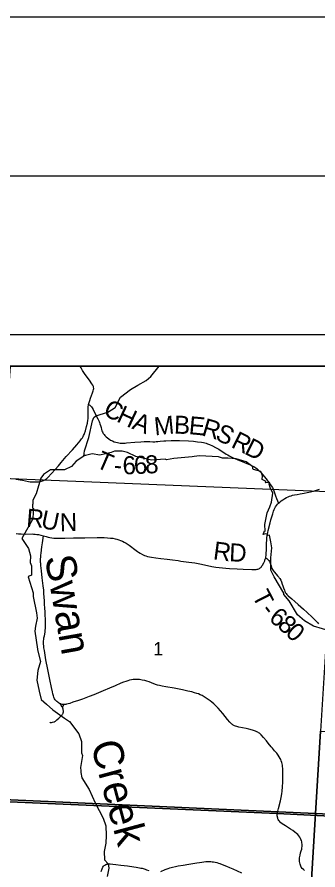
# Model space of a CAD drawing. Extents: x -2.1 to 31.9, y 6.3 to 28.3.
# Drawn here: x 4.749 to 5.698, y 25.658 to 28.344 of the extents above; entities that cross this region are included whole.
import ezdxf

# ---------------------------------------------------------------- set-up
doc = ezdxf.new("R2010")
doc.units = 0
for name, color, linetype in [('Default', 7, 'Continuous'), ('GM_X_County_Road', 7, 'Continuous'), ('GM_X_County_Road_Text', 7, 'Continuous'), ('GM_X_Minor_River', 7, 'Continuous'), ('GM_X_Minor_River_Text', 7, 'Continuous'), ('GM_X_Section', 7, 'Continuous'), ('GM_X_Section_Text', 7, 'Continuous'), ('GM_X_Township_Road', 7, 'Continuous'), ('GM_X_Township_Road_Text', 7, 'Continuous'), ('SH_Border', 7, 'Continuous'), ('SH_Cut_Line', 7, 'Continuous'), ('SH_Data', 7, 'Continuous')]:
    doc.layers.add(name, color=color, linetype=linetype)

msp = doc.modelspace()

# ---------------------------------------------------------------- linework, layer by layer
at = {"layer": 'Default'}
for points in [[(4.6286, 25.8765), (5.5694, 25.8349), (6.8344, 25.7721), (6.8344, 27.244), (4.7331, 27.244)], [(6.8344, 20.444), (6.8344, 25.7721), (5.5694, 25.8349), (4.6286, 25.8765), (4.6032, 25.4816), (4.5667, 24.9084), (4.5473, 24.5954), (4.4901, 23.6442), (4.4651, 23.2405)]]:
    msp.add_lwpolyline(points, dxfattribs=at)
msp.add_lwpolyline([(5.7794, 27.244), (4.7272, 27.244), (4.7032, 26.892), (5.7545, 26.8487), (5.7699, 27.0924)], close=True, dxfattribs=at)
at = {"layer": 'GM_X_County_Road'}
for points in [[(4.7452, 26.8886), (4.7657, 26.8849), (4.7854, 26.8812), (4.7904, 26.8805), (4.7945, 26.8801), (4.7987, 26.8798), (4.8026, 26.8796), (4.8072, 26.8797), (4.8118, 26.8801), (4.8161, 26.8805), (4.8205, 26.8812), (4.8259, 26.8824), (4.829, 26.8832), (4.8325, 26.8845), (4.8348, 26.8855), (4.8366, 26.8864), (4.8393, 26.8881), (4.8417, 26.89), (4.8454, 26.8937), (4.8574, 26.9059), (4.8694, 26.9192), (4.8791, 26.9304), (4.888, 26.9407), (4.9042, 26.9595), (4.9235, 26.9807), (4.9379, 26.9971), (4.948, 27.0094), (4.9526, 27.0154), (4.955, 27.0188), (4.9571, 27.0225), (4.9589, 27.0258), (4.9604, 27.0292), (4.9618, 27.0326), (4.9646, 27.0409), (4.9681, 27.0539), (4.9706, 27.0653), (4.9723, 27.0743), (4.9729, 27.0785), (4.9732, 27.0826), (4.9733, 27.0867), (4.9734, 27.0942), (4.9732, 27.1063), (4.9734, 27.1138), (4.9736, 27.1175), (4.9741, 27.1216), (4.9747, 27.1241), (4.9751, 27.1264), (4.9761, 27.1302), (4.9781, 27.1362), (4.9809, 27.144), (4.9868, 27.1599), (4.9892, 27.167), (4.9901, 27.1705), (4.9906, 27.1744), (4.9904, 27.1779), (4.99, 27.18), (4.9894, 27.1815), (4.9878, 27.1844), (4.9848, 27.1887), (4.977, 27.1999), (4.964, 27.2182), (4.9552, 27.2311), (4.9509, 27.2386), (4.9482, 27.244)], [(4.7463, 26.717), (4.7537, 26.7163), (4.7619, 26.7159), (4.7763, 26.7157), (4.7961, 26.7158), (4.8011, 26.7155), (4.806, 26.7152), (4.8113, 26.7146), (4.817, 26.7137), (4.8236, 26.7122), (4.8318, 26.71), (4.841, 26.7074), (4.8468, 26.706), (4.8524, 26.7047), (4.8586, 26.7036), (4.8648, 26.7029), (4.8706, 26.7026), (4.8781, 26.7024), (4.8998, 26.7027), (4.9266, 26.7032), (4.9623, 26.7035), (5.0014, 26.7042), (5.0126, 26.7042), (5.0236, 26.7042), (5.0346, 26.7039), (5.0436, 26.7031), (5.0507, 26.7021), (5.0578, 26.7008), (5.0634, 26.6994), (5.0695, 26.6976), (5.0756, 26.6954), (5.0814, 26.6929), (5.0869, 26.6902), (5.0928, 26.6867), (5.102, 26.6802), (5.1242, 26.6642), (5.1287, 26.6611), (5.1318, 26.6589), (5.1371, 26.6555), (5.144, 26.6516), (5.1507, 26.6484), (5.1553, 26.6465), (5.1605, 26.6448), (5.1665, 26.6434), (5.1731, 26.6423), (5.1867, 26.6406), (5.2027, 26.639), (5.222, 26.6367), (5.2391, 26.6344), (5.2569, 26.6318), (5.2652, 26.6306), (5.2904, 26.6275), (5.3003, 26.626), (5.3093, 26.6245), (5.3307, 26.6206), (5.3636, 26.6138), (5.376, 26.6114), (5.3864, 26.6099), (5.3969, 26.6087), (5.4071, 26.6079), (5.4193, 26.6071), (5.4427, 26.606), (5.4619, 26.6053), (5.4893, 26.6037), (5.4947, 26.6035), (5.4994, 26.6038), (5.5025, 26.604), (5.5057, 26.6046), (5.5085, 26.6054), (5.511, 26.6064), (5.5132, 26.6075), (5.5155, 26.609), (5.5175, 26.6107), (5.5194, 26.6128), (5.5214, 26.6153), (5.523, 26.6178), (5.5268, 26.6248), (5.5299, 26.6313), (5.5308, 26.6335), (5.5317, 26.636), (5.5325, 26.6384), (5.5331, 26.6411), (5.5337, 26.6443), (5.5342, 26.6482), (5.5345, 26.652), (5.5354, 26.6683), (5.5361, 26.6857), (5.5367, 26.6978), (5.5371, 26.7047), (5.5376, 26.7095), (5.5384, 26.7148), (5.5395, 26.7206), (5.5411, 26.7272), (5.5471, 26.7505), (5.5497, 26.7601), (5.5525, 26.7701), (5.5553, 26.7793), (5.5581, 26.7879), (5.56, 26.7929), (5.5619, 26.7972), (5.5645, 26.8017), (5.5673, 26.8058), (5.5707, 26.8101), (5.5739, 26.8133), (5.5776, 26.8165), (5.5823, 26.82), (5.5875, 26.8236), (5.5934, 26.8274), (5.5989, 26.8305), (5.6036, 26.8328), (5.6082, 26.8347), (5.6129, 26.8364), (5.6175, 26.8378), (5.6235, 26.8391), (5.6324, 26.8406), (5.6421, 26.8421), (5.6542, 26.844), (5.6643, 26.846), (5.674, 26.8482), (5.6838, 26.8508), (5.6934, 26.8536), (5.7027, 26.8569)], [(5.5696, 25.8343), (5.5698, 25.8361), (5.5703, 25.8393), (5.5709, 25.8425), (5.5733, 25.8514), (5.5794, 25.8749), (5.5827, 25.8912), (5.5839, 25.898), (5.5848, 25.9042), (5.5853, 25.9085), (5.5861, 25.916), (5.5865, 25.9232), (5.587, 25.93), (5.5871, 25.937), (5.5873, 25.9507), (5.5873, 25.9656), (5.5872, 25.973), (5.587, 25.9779), (5.5865, 25.9827), (5.5858, 25.9874), (5.5848, 25.9921), (5.5836, 25.9963), (5.5821, 26.0008), (5.5804, 26.0053), (5.5785, 26.009), (5.5759, 26.0135), (5.5723, 26.0189), (5.5679, 26.0249), (5.5612, 26.0331), (5.5543, 26.0411), (5.5506, 26.0453), (5.5406, 26.0572), (5.5351, 26.0639), (5.5257, 26.0752), (5.5186, 26.0832), (5.5159, 26.0858), (5.5133, 26.088), (5.5107, 26.0899), (5.508, 26.0915), (5.5048, 26.0931), (5.5014, 26.0944), (5.4977, 26.0957), (5.4913, 26.0976), (5.4796, 26.1006), (5.4712, 26.1026), (5.4481, 26.1076), (5.4422, 26.1091), (5.4381, 26.1103), (5.4346, 26.1117), (5.431, 26.1135), (5.4283, 26.1152), (5.4263, 26.1169), (5.4241, 26.1187), (5.4204, 26.1227), (5.413, 26.1317), (5.3975, 26.1507), (5.3829, 26.1674), (5.3752, 26.1756), (5.3698, 26.1808), (5.3636, 26.1861), (5.3576, 26.1906), (5.3484, 26.197), (5.3391, 26.2028), (5.3322, 26.2066), (5.3265, 26.2096), (5.3213, 26.2118), (5.3163, 26.2136), (5.3086, 26.2159), (5.2996, 26.2183), (5.288, 26.221), (5.2704, 26.2248), (5.2439, 26.23), (5.2185, 26.2344), (5.2063, 26.2365), (5.1979, 26.2384), (5.1919, 26.24), (5.1855, 26.2422), (5.1726, 26.2471), (5.1654, 26.2497), (5.1583, 26.2521), (5.1515, 26.2539), (5.1435, 26.2558), (5.1349, 26.2571), (5.1297, 26.2575), (5.1243, 26.2577), (5.1196, 26.2576), (5.1146, 26.2571), (5.1095, 26.2565), (5.1038, 26.2553), (5.0978, 26.2537), (5.0915, 26.2515), (5.0844, 26.2488), (5.0758, 26.2454), (5.0579, 26.2373), (5.0407, 26.2297), (5.0205, 26.2214), (4.9905, 26.2093), (4.9764, 26.2036), (4.955, 26.1959), (4.9422, 26.1914), (4.9251, 26.1856), (4.9152, 26.1822), (4.9105, 26.1808), (4.9051, 26.1795), (4.9028, 26.179), (4.8998, 26.1787), (4.8968, 26.1787), (4.8941, 26.1789), (4.8916, 26.1792), (4.8883, 26.1799), (4.8866, 26.1805), (4.8851, 26.1811), (4.8825, 26.1822), (4.8798, 26.1839), (4.877, 26.1858), (4.8746, 26.1877), (4.8724, 26.1899), (4.8706, 26.1919), (4.8691, 26.1938), (4.8672, 26.1969), (4.8651, 26.2013), (4.8633, 26.2065), (4.8619, 26.2118), (4.8602, 26.2191), (4.8575, 26.2318), (4.8519, 26.2578), (4.8454, 26.2892), (4.8399, 26.3192), (4.8373, 26.3345), (4.8349, 26.3492), (4.8338, 26.3568), (4.8329, 26.3634), (4.8324, 26.3685), (4.8324, 26.3722), (4.8324, 26.3759), (4.8326, 26.3797), (4.833, 26.3834), (4.8338, 26.3889), (4.835, 26.395), (4.8361, 26.4005), (4.8373, 26.4074), (4.8379, 26.413), (4.8383, 26.418), (4.8385, 26.4239), (4.8385, 26.4307), (4.8384, 26.4394), (4.8383, 26.4487), (4.838, 26.4587), (4.8377, 26.4637), (4.8373, 26.4705), (4.8363, 26.4825), (4.8352, 26.4946), (4.8349, 26.5039), (4.8345, 26.5175), (4.8338, 26.5269), (4.8329, 26.5386), (4.8315, 26.5529), (4.8295, 26.5689), (4.8285, 26.5775), (4.8257, 26.5997), (4.8239, 26.6161), (4.8234, 26.6224), (4.8231, 26.6263), (4.8229, 26.6302), (4.8229, 26.634), (4.8231, 26.6378), (4.8234, 26.6427), (4.824, 26.6488), (4.8248, 26.655), (4.8274, 26.6752), (4.8291, 26.6881), (4.8308, 26.7021), (4.8318, 26.71)], [(5.6551, 25.6555), (5.652, 25.6585), (5.6483, 25.6626), (5.6453, 25.6668), (5.6437, 25.6697), (5.6425, 25.6727), (5.6414, 25.6762), (5.6406, 25.6799), (5.6401, 25.6838), (5.6399, 25.6877), (5.6399, 25.6917), (5.6402, 25.6958), (5.6407, 25.6998), (5.6415, 25.7041), (5.6432, 25.711), (5.6451, 25.7178), (5.6466, 25.7234), (5.6474, 25.7273), (5.648, 25.7313), (5.6483, 25.7352), (5.648, 25.7391), (5.6474, 25.7431), (5.6466, 25.7466), (5.6456, 25.7501), (5.6444, 25.7534), (5.643, 25.7566), (5.6405, 25.761), (5.6374, 25.765), (5.634, 25.7688), (5.6299, 25.7726), (5.6251, 25.7766), (5.6186, 25.7815), (5.6113, 25.7864), (5.5955, 25.7963), (5.5854, 25.8029), (5.5812, 25.8061), (5.5783, 25.8086), (5.5762, 25.811), (5.5745, 25.8135), (5.5727, 25.8166), (5.5716, 25.819), (5.5709, 25.8211), (5.5702, 25.8234), (5.5698, 25.8255), (5.5695, 25.8274), (5.5694, 25.8296), (5.5694, 25.8317), (5.5696, 25.8343)]]:
    msp.add_lwpolyline(points, dxfattribs=at)
at = {"layer": 'GM_X_Minor_River'}
for points in [[(4.9591, 26.9608), (4.9616, 26.9774), (4.9753, 27.0199), (4.9864, 27.0719), (4.9912, 27.0828), (4.9974, 27.0875), (5.0348, 27.0992), (5.0579, 27.1144), (5.0752, 27.1466), (5.1065, 27.1706), (5.1296, 27.1843), (5.1557, 27.1987), (5.1709, 27.2122), (5.1975, 27.244)], [(5.1732, 26.9484), (5.124, 26.9597), (5.0975, 26.9722), (5.0801, 26.9771), (5.0563, 26.9762), (5.0454, 26.9724), (5.0095, 26.9636), (4.986, 26.9681), (4.9649, 26.9633)], [(4.9653, 26.9633), (4.9626, 26.9631), (4.9592, 26.9608), (4.935, 26.9456), (4.9207, 26.9284), (4.8987, 26.918)], [(5.5453, 26.7123), (5.5397, 26.7109), (5.5386, 26.7139), (5.5333, 26.7158), (5.5246, 26.7146), (5.5295, 26.7257), (5.5318, 26.7249), (5.5299, 26.7454), (5.5374, 26.782), (5.5464, 26.801), (5.5517, 26.8158), (5.5551, 26.8443), (5.5475, 26.8618), (5.5445, 26.8732), (5.546, 26.8778), (5.532, 26.8766), (5.5331, 26.8793), (5.5328, 26.8819), (5.5222, 26.8872), (5.5233, 26.899), (5.5195, 26.9081), (5.518, 26.9127), (5.4949, 26.9191), (5.4923, 26.921), (5.4923, 26.9275), (5.4718, 26.943), (5.4401, 26.952), (5.4136, 26.955), (5.397, 26.9542), (5.3841, 26.9591), (5.324, 26.9624), (5.3074, 26.9601), (5.3009, 26.9593), (5.2431, 26.9531), (5.2197, 26.9493), (5.2159, 26.9511), (5.1732, 26.9484)], [(4.8987, 26.918), (4.8545, 26.9176), (4.8417, 26.9092), (4.8319, 26.9027), (4.8239, 26.8921), (4.8164, 26.8677), (4.8089, 26.8422), (4.7991, 26.8228), (4.7983, 26.811), (4.798, 26.808), (4.798, 26.7977), (4.8002, 26.7962), (4.7984, 26.7662), (4.7972, 26.7616)], [(4.7972, 26.7616), (4.7644, 26.7011), (4.7849, 26.6696), (4.7909, 26.6468), (4.7902, 26.6263), (4.794, 26.6153), (4.7944, 26.5856), (4.7869, 26.5829), (4.7842, 26.581), (4.7994, 26.5305), (4.7994, 26.5191), (4.8104, 26.467), (4.8123, 26.4511), (4.8071, 26.4256), (4.8048, 26.41), (4.8136, 26.353), (4.8132, 26.3511), (4.8223, 26.3146), (4.814, 26.2853), (4.8114, 26.2553), (4.8186, 26.2207), (4.8254, 26.1949), (4.8417, 26.1797), (4.8614, 26.1619), (4.8988, 26.1358), (4.914, 26.1256), (4.9442, 26.0868), (4.9526, 26.0625), (4.9522, 26.0261), (4.9553, 26.0181), (4.9489, 25.9801), (4.9497, 25.9698), (4.95, 25.9641), (4.9531, 25.9474), (4.9762, 25.9109), (4.9947, 25.8688), (5.0205, 25.821), (5.0288, 25.7967), (5.0304, 25.7666), (5.0289, 25.7415), (5.0232, 25.7161), (5.0244, 25.6898), (5.0361, 25.6769), (5.0388, 25.6637), (5.0328, 25.6374)], [(5.8691, 26.3117), (5.86, 26.3303), (5.8452, 26.3505), (5.8005, 26.3933), (5.7911, 26.4005), (5.7446, 26.4084), (5.7408, 26.4084), (5.6841, 26.4253), (5.6557, 26.442), (5.6338, 26.4613), (5.6069, 26.5054), (5.5906, 26.5251), (5.5906, 26.5293), (5.5595, 26.5809), (5.5489, 26.6014), (5.5493, 26.6409), (5.5526, 26.6717), (5.5488, 26.6907), (5.5453, 26.7123)]]:
    msp.add_lwpolyline(points, dxfattribs=at)
at = {"layer": 'GM_X_Section'}
for points in [[(4.7032, 26.892), (5.7545, 26.8487), (5.7377, 26.5914), (5.7216, 26.3472), (5.7057, 26.0946), (5.6902, 25.8357), (4.6345, 25.8828)], [(5.7057, 26.0946), (6.7462, 26.0413), (6.7308, 25.7856), (5.6902, 25.8357)], [(4.6345, 25.8828), (5.6902, 25.8357), (5.6296, 24.8273), (4.5692, 24.8661)], [(6.7308, 25.7856), (6.674, 24.7794), (5.6296, 24.8273), (5.6902, 25.8357)]]:
    msp.add_lwpolyline(points, close=True, dxfattribs=at)
at = {"layer": 'GM_X_Township_Road'}
for points in [[(4.9747, 27.1241), (4.9782, 27.1219), (4.981, 27.1194), (4.9834, 27.1166), (4.9856, 27.1135), (4.9889, 27.1077), (4.9967, 27.0921), (5.0034, 27.079), (5.0055, 27.0748), (5.0074, 27.0705), (5.009, 27.0665), (5.0104, 27.0628), (5.012, 27.0576), (5.0137, 27.0511), (5.0152, 27.045), (5.0167, 27.0405), (5.018, 27.0374), (5.0192, 27.0348), (5.0208, 27.0321), (5.0232, 27.0291), (5.0262, 27.0256), (5.0299, 27.022), (5.0342, 27.0183), (5.0387, 27.015), (5.0439, 27.0117), (5.0495, 27.0089), (5.0555, 27.0065), (5.0604, 27.0048), (5.0652, 27.0036), (5.0694, 27.0028), (5.0737, 27.0023), (5.0788, 27.002), (5.0839, 27.002), (5.0894, 27.0021), (5.0943, 27.0024), (5.1201, 27.0048), (5.1392, 27.0063), (5.1494, 27.0068), (5.1563, 27.0068), (5.1681, 27.0066), (5.1772, 27.0063), (5.183, 27.0064), (5.188, 27.0066), (5.1929, 27.0069), (5.2001, 27.0077), (5.2123, 27.0089), (5.2179, 27.0093), (5.2353, 27.0101), (5.2495, 27.0104), (5.2613, 27.0102), (5.2894, 27.0089), (5.3054, 27.0077), (5.3179, 27.0064), (5.3309, 27.0047), (5.3365, 27.0038), (5.3407, 27.0029), (5.3448, 27.0018), (5.3497, 27.0001), (5.3562, 26.9972), (5.3652, 26.9931), (5.3746, 26.9883), (5.3849, 26.9826), (5.3923, 26.9781), (5.4042, 26.9705), (5.4089, 26.9675), (5.4136, 26.9646), (5.4179, 26.9621), (5.4239, 26.9588), (5.4306, 26.9556), (5.4426, 26.9504), (5.4659, 26.941), (5.4836, 26.9338), (5.4902, 26.9308), (5.4959, 26.928), (5.4989, 26.9262), (5.5018, 26.9244), (5.5061, 26.921), (5.5107, 26.9169), (5.5156, 26.9121), (5.5194, 26.9078), (5.5233, 26.9032), (5.5345, 26.8891), (5.5443, 26.8763), (5.5511, 26.8668), (5.5532, 26.8635), (5.5549, 26.8608), (5.5563, 26.858), (5.5576, 26.8548), (5.5642, 26.8363), (5.5674, 26.8277), (5.5708, 26.8199), (5.5739, 26.8133)], [(5.5331, 26.6411), (5.5363, 26.6387), (5.5388, 26.6367), (5.541, 26.6346), (5.5432, 26.6321), (5.545, 26.6295), (5.5463, 26.627), (5.5475, 26.6241), (5.5487, 26.6204), (5.5501, 26.615), (5.5513, 26.6109), (5.5526, 26.6075), (5.5543, 26.6043), (5.5567, 26.6007), (5.5602, 26.5964), (5.5663, 26.5897), (5.5708, 26.5844), (5.5744, 26.5799), (5.576, 26.5777), (5.5774, 26.5752), (5.5803, 26.5699), (5.5825, 26.5649), (5.5853, 26.5577), (5.5875, 26.5521), (5.5894, 26.5465), (5.5919, 26.5389), (5.5938, 26.5343), (5.5958, 26.5306), (5.5975, 26.5279), (5.5994, 26.5254), (5.6015, 26.5231), (5.6039, 26.5206), (5.6155, 26.5113), (5.6252, 26.5028), (5.6356, 26.4935), (5.6521, 26.4785), (5.6634, 26.4683), (5.6794, 26.4541), (5.6852, 26.4485), (5.6896, 26.4443), (5.6938, 26.4397), (5.6974, 26.4359), (5.6998, 26.4329)], [(4.8521, 26.1227), (4.8538, 26.1223), (4.8556, 26.1221), (4.8575, 26.1223), (4.8611, 26.1229), (4.8645, 26.1237), (4.8665, 26.1244), (4.8682, 26.1251), (4.8697, 26.1261), (4.8709, 26.127), (4.8745, 26.1305), (4.8803, 26.136), (4.8908, 26.146), (4.8924, 26.1478), (4.8935, 26.1496), (4.8943, 26.1512), (4.8947, 26.153), (4.895, 26.1548), (4.8951, 26.1567), (4.8951, 26.159), (4.8948, 26.1611), (4.8943, 26.1635), (4.8934, 26.1674), (4.8932, 26.1692), (4.8936, 26.1716), (4.8942, 26.1736), (4.8952, 26.1758), (4.8968, 26.1787)], [(4.8932, 26.1692), (4.8912, 26.1714), (4.8892, 26.174), (4.8871, 26.177), (4.8851, 26.1811)], [(5.2023, 25.6528), (5.2165, 25.6588), (5.2252, 25.6621), (5.231, 25.664), (5.2392, 25.6664), (5.2482, 25.6686), (5.2572, 25.6703), (5.2725, 25.6729), (5.2906, 25.6758), (5.3164, 25.68), (5.3243, 25.6814), (5.332, 25.6826), (5.338, 25.6834), (5.3442, 25.6838), (5.3495, 25.6839), (5.3548, 25.6838), (5.3597, 25.6837), (5.3647, 25.6834), (5.3689, 25.6828), (5.3738, 25.6819), (5.3792, 25.6806), (5.3843, 25.6792), (5.3888, 25.6777), (5.396, 25.675), (5.409, 25.6697), (5.4192, 25.6654), (5.4296, 25.661), (5.4566, 25.6483)], [(5.014, 25.6522), (5.0172, 25.661), (5.0185, 25.6641), (5.0199, 25.6667), (5.0216, 25.6691), (5.0238, 25.6713), (5.0258, 25.6728), (5.0285, 25.6744), (5.0309, 25.6754), (5.0331, 25.676), (5.0355, 25.6765), (5.039, 25.6767), (5.0424, 25.6766), (5.0509, 25.6758), (5.0608, 25.6749), (5.0766, 25.673), (5.0976, 25.6702), (5.1173, 25.6677), (5.1247, 25.6667), (5.13, 25.6657), (5.1349, 25.6646), (5.1391, 25.6637), (5.143, 25.6627), (5.1465, 25.6618), (5.1529, 25.6598), (5.1576, 25.6583), (5.1641, 25.656)]]:
    msp.add_lwpolyline(points, dxfattribs=at)
at = {"layer": 'SH_Border'}
msp.add_lwpolyline([(-0.5656, 27.844), (31.4344, 27.844), (31.4344, 6.844), (-0.5656, 6.844)], close=True, dxfattribs=at)
at = {"layer": 'SH_Cut_Line'}
msp.add_lwpolyline([(-2.0656, 6.344), (31.9344, 6.344), (31.9344, 28.344), (-2.0656, 28.344)], close=True, dxfattribs=at)
msp.add_lwpolyline([(6.8344, 20.444), (6.8344, 27.244), (0.0344, 27.244), (0.0344, 20.444)], dxfattribs=at)
at = {"layer": 'SH_Data'}
for p, q in [((-0.0656, 27.344), (6.9344, 27.344)), ((0.0344, 27.244), (6.8344, 27.244))]:
    msp.add_line(p, q, dxfattribs=at)

# ---------------------------------------------------------------- texts
at = {"layer": 'GM_X_County_Road_Text'}
for s, rotation, p in [('R', 355.5284, (4.7767, 26.7391)), ('U', 348.12, (4.8213, 26.7358)), ('N', 1.5663, (4.8844, 26.7242)), ('R', 352.3865, (5.3653, 26.6365)), ('D', 357.4753, (5.417, 26.6299))]:
    msp.add_text(s, height=0.0568, rotation=rotation, dxfattribs=at).set_placement(p)
at = {"layer": 'GM_X_Minor_River_Text'}
for s, height, rotation, p in [('Swan', 0.09471, 280.0039, (4.8362, 26.6424)), ('Creek', 0.0947, 285.0007, (4.9805, 26.0537))]:
    msp.add_text(s, height=height, rotation=rotation, dxfattribs=at).set_placement(p)
at = {"layer": 'GM_X_Section_Text'}
msp.add_text('1', height=0.0419, rotation=0, dxfattribs=at).set_placement((5.1787, 26.3334))
at = {"layer": 'GM_X_Township_Road_Text'}
for s, rotation, p in [('C', 334.8489, (5.0173, 27.0911)), ('H', 334.8614, (5.0596, 27.0713)), ('A', 338.441, (5.1084, 27.0485)), ('M', 5.6603, (5.1838, 27.0261)), ('B', 357.9564, (5.2432, 27.0321)), ('E', 354.6762, (5.289, 27.0305)), ('R', 343.6638, (5.3285, 27.0271)), ('S', 334.1447, (5.3709, 27.0149)), ('R', 333.7073, (5.421, 26.9905)), ('D', 333.2509, (5.4627, 26.9698)), ('T', 336.4666, (4.9939, 26.9274)), ('6', 1.1802, (5.0821, 26.9035)), ('6', 2.5747, (5.1186, 26.9042)), ('8', 2.9936, (5.154, 26.9058)), ('-', 355.5144, (5.0527, 26.9055)), ('T', 297.2569, (5.4889, 26.5216)), ('-', 307.6766, (5.5144, 26.4743)), ('6', 322.5593, (5.54, 26.4446)), ('8', 317.831, (5.5669, 26.4241)), ('0', 316.5439, (5.5925, 26.4008))]:
    msp.add_text(s, height=0.0568, rotation=rotation, dxfattribs=at).set_placement(p)

doc.saveas('drawing.dxf')
